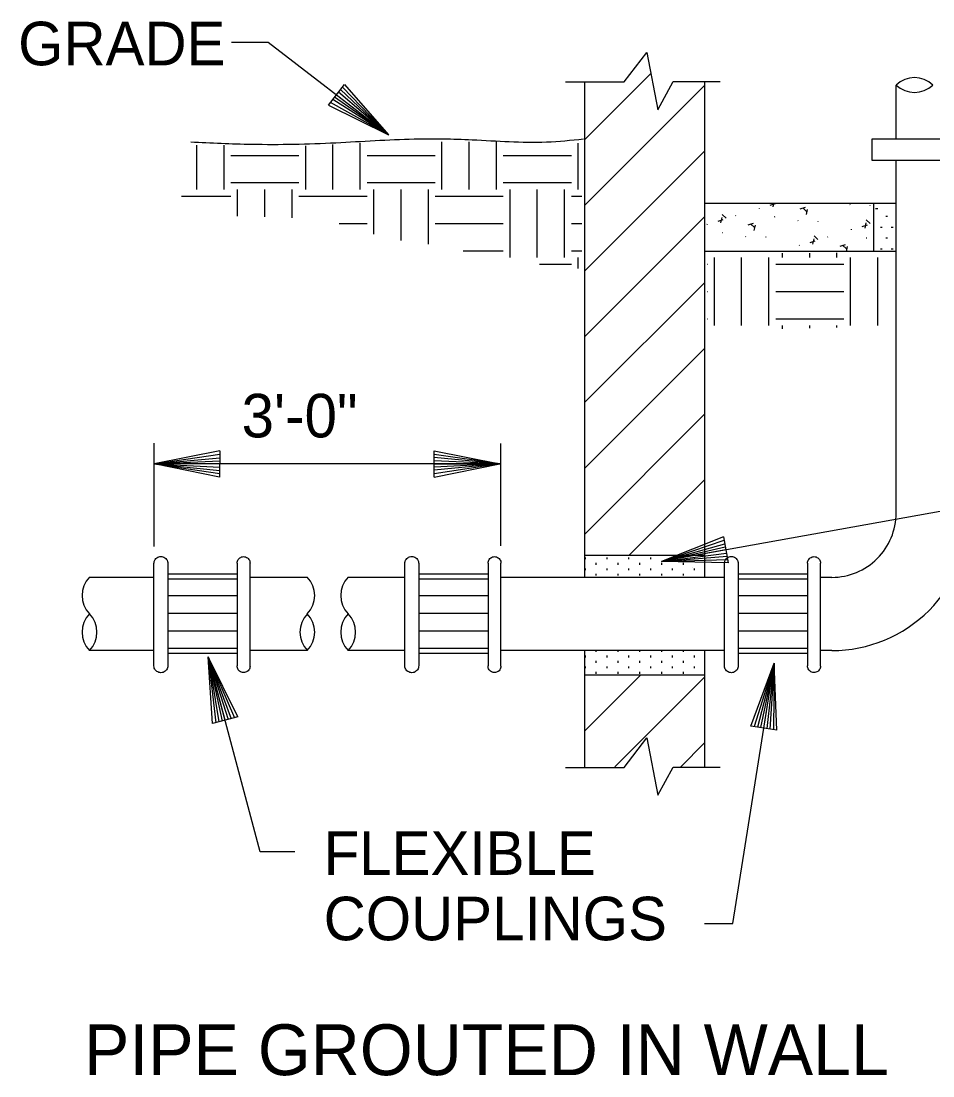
# Model space of a CAD drawing. Extents: x 10040.55 to 10045.84, y 10033.26 to 10035.76.
# Drawn here: x 10041.296 to 10041.5052, y 10033.7217 to 10033.9638 of the extents above; entities that cross this region are included whole.
import ezdxf

# ---------------------------------------------------------------- set-up
doc = ezdxf.new("R2010")
doc.units = 0
doc.layers.add('Level 2', color=7, linetype='Continuous')

msp = doc.modelspace()

# ---------------------------------------------------------------- linework, layer by layer
at = {"layer": 'Level 2'}
for p, q in [((10041.42536, 10033.93666), (10041.4405, 10033.95179)), ((10041.36655, 10033.9445), (10041.37023, 10033.94928)), ((10041.37023, 10033.94928), (10041.38032, 10033.93772)), ((10041.42536, 10033.83615), (10041.42536, 10033.94986)), ((10041.42538, 10033.92157), (10041.4528, 10033.94901)), ((10041.4528, 10033.94986), (10041.4528, 10033.83615)), ((10041.49676, 10033.93668), (10041.49676, 10033.94913)), ((10041.36835, 10033.94688), (10041.38032, 10033.93772)), ((10041.38032, 10033.93772), (10041.36882, 10033.94747)), ((10041.38032, 10033.93772), (10041.36927, 10033.94806)), ((10041.38032, 10033.93772), (10041.36972, 10033.94864)), ((10041.36655, 10033.9445), (10041.38032, 10033.93772)), ((10041.38032, 10033.93772), (10041.36702, 10033.94511)), ((10041.38032, 10033.93772), (10041.36751, 10033.94579)), ((10041.38032, 10033.93772), (10041.36794, 10033.94631)), ((10041.33632, 10033.92517), (10041.33632, 10033.9353)), ((10041.34257, 10033.92517), (10041.34257, 10033.9353)), ((10041.36132, 10033.92517), (10041.36132, 10033.93514)), ((10041.36757, 10033.92517), (10041.36757, 10033.93546)), ((10041.37382, 10033.92517), (10041.37382, 10033.93577)), ((10041.39257, 10033.92517), (10041.39257, 10033.93607)), ((10041.39882, 10033.92517), (10041.39882, 10033.93609)), ((10041.40507, 10033.92517), (10041.40507, 10033.9362)), ((10041.42382, 10033.92517), (10041.42382, 10033.93582)), ((10041.34414, 10033.93298), (10041.35976, 10033.93298)), ((10041.37539, 10033.93298), (10041.39101, 10033.93298)), ((10041.40664, 10033.93298), (10041.42226, 10033.93298)), ((10041.42538, 10033.90649), (10041.4528, 10033.93393)), ((10041.49676, 10033.85089), (10041.49676, 10033.93191)), ((10041.34414, 10033.92673), (10041.35976, 10033.92673)), ((10041.3457, 10033.91904), (10041.3457, 10033.92517)), ((10041.35195, 10033.91885), (10041.35195, 10033.92517)), ((10041.3582, 10033.91866), (10041.3582, 10033.92517)), ((10041.37539, 10033.92673), (10041.39101, 10033.92673)), ((10041.37695, 10033.9149), (10041.37695, 10033.92517)), ((10041.3832, 10033.91343), (10041.3832, 10033.92517)), ((10041.38945, 10033.91257), (10041.38945, 10033.92517)), ((10041.40664, 10033.92673), (10041.42226, 10033.92673)), ((10041.4082, 10033.90954), (10041.4082, 10033.92517)), ((10041.41445, 10033.90954), (10041.41445, 10033.92517)), ((10041.4207, 10033.90954), (10041.4207, 10033.92517)), ((10041.33285, 10033.9236), (10041.34414, 10033.9236)), ((10041.35976, 10033.9236), (10041.37539, 10033.9236)), ((10041.39101, 10033.9236), (10041.40664, 10033.9236)), ((10041.42226, 10033.9236), (10041.42464, 10033.9236)), ((10041.4968, 10033.92197), (10041.4528, 10033.92197)), ((10041.4654, 10033.92079), (10041.46542, 10033.9209)), ((10041.46788, 10033.92156), (10041.46907, 10033.92193)), ((10041.46864, 10033.92197), (10041.46845, 10033.92116)), ((10041.4759, 10033.92099), (10041.4747, 10033.92063)), ((10041.47533, 10033.92092), (10041.47624, 10033.92007)), ((10041.47619, 10033.91938), (10041.47647, 10033.92059)), ((10041.48623, 10033.92161), (10041.48616, 10033.92169)), ((10041.49077, 10033.92156), (10041.49075, 10033.92146)), ((10041.49161, 10033.92197), (10041.49161, 10033.911)), ((10041.49206, 10033.92076), (10041.4926, 10033.92076)), ((10041.42538, 10033.89142), (10041.4528, 10033.91884)), ((10041.45593, 10033.91791), (10041.45711, 10033.91827)), ((10041.45676, 10033.91872), (10041.45648, 10033.91751)), ((10041.45774, 10033.91856), (10041.45683, 10033.91941)), ((10041.45991, 10033.91913), (10041.46003, 10033.91916)), ((10041.46892, 10033.91885), (10041.46882, 10033.91882)), ((10041.47427, 10033.91796), (10041.4742, 10033.91803)), ((10041.47881, 10033.91791), (10041.47879, 10033.91781)), ((10041.48983, 10033.9175), (10041.48955, 10033.91628)), ((10041.4908, 10033.91735), (10041.48989, 10033.91821)), ((10041.49441, 10033.91904), (10041.49482, 10033.91904)), ((10041.36897, 10033.91735), (10041.37539, 10033.91735)), ((10041.39101, 10033.91735), (10041.40664, 10033.91735)), ((10041.42226, 10033.91735), (10041.42464, 10033.91735)), ((10041.45344, 10033.91715), (10041.45346, 10033.91724)), ((10041.45697, 10033.9152), (10041.45686, 10033.91517)), ((10041.46394, 10033.91733), (10041.46274, 10033.91697)), ((10041.46338, 10033.91726), (10041.46428, 10033.91641)), ((10041.46423, 10033.91572), (10041.46451, 10033.91694)), ((10041.48651, 10033.91592), (10041.48653, 10033.91602)), ((10041.48898, 10033.91668), (10041.49017, 10033.91704)), ((10041.49316, 10033.91654), (10041.49357, 10033.91654)), ((10041.49566, 10033.91654), (10041.49607, 10033.91654)), ((10041.46231, 10033.91429), (10041.46224, 10033.91436)), ((10041.46685, 10033.91426), (10041.46683, 10033.91416)), ((10041.47702, 10033.91302), (10041.47822, 10033.9134)), ((10041.47788, 10033.91385), (10041.47759, 10033.91264)), ((10041.47884, 10033.9137), (10041.47793, 10033.91454)), ((10041.481, 10033.91424), (10041.48113, 10033.91428)), ((10041.49002, 10033.91398), (10041.48992, 10033.91395)), ((10041.49441, 10033.91404), (10041.49482, 10033.91404)), ((10041.39747, 10033.9111), (10041.40664, 10033.9111)), ((10041.42226, 10033.9111), (10041.42464, 10033.9111)), ((10041.4528, 10033.91099), (10041.4968, 10033.91099)), ((10041.4707, 10033.90954), (10041.4707, 10033.91051)), ((10041.47454, 10033.91227), (10041.47457, 10033.91236)), ((10041.47695, 10033.90954), (10041.47695, 10033.91056)), ((10041.4832, 10033.90954), (10041.4832, 10033.91061)), ((10041.48504, 10033.91246), (10041.48384, 10033.91209)), ((10041.48447, 10033.9124), (10041.48539, 10033.91154)), ((10041.48535, 10033.91092), (10041.48561, 10033.91206)), ((10041.49316, 10033.91154), (10041.49357, 10033.91154)), ((10041.49566, 10033.91154), (10041.49607, 10033.91154)), ((10041.41493, 10033.90798), (10041.42226, 10033.90798)), ((10041.42382, 10033.90699), (10041.42382, 10033.90954)), ((10041.45343, 10033.90798), (10041.45351, 10033.90798)), ((10041.45507, 10033.89392), (10041.45507, 10033.90954)), ((10041.46132, 10033.89392), (10041.46132, 10033.90954)), ((10041.46757, 10033.89392), (10041.46757, 10033.90954)), ((10041.46914, 10033.90798), (10041.48476, 10033.90798)), ((10041.48632, 10033.89392), (10041.48632, 10033.90954)), ((10041.49257, 10033.89392), (10041.49257, 10033.90954)), ((10041.42538, 10033.87633), (10041.4528, 10033.90376)), ((10041.45343, 10033.90173), (10041.45351, 10033.90173)), ((10041.46914, 10033.90173), (10041.48476, 10033.90173)), ((10041.45343, 10033.89548), (10041.45351, 10033.89548)), ((10041.46914, 10033.89548), (10041.48476, 10033.89548)), ((10041.4707, 10033.89316), (10041.4707, 10033.89392)), ((10041.47695, 10033.89332), (10041.47695, 10033.89392)), ((10041.4832, 10033.89349), (10041.4832, 10033.89392)), ((10041.42539, 10033.86125), (10041.4528, 10033.88867)), ((10041.42539, 10033.84617), (10041.45281, 10033.87358)), ((10041.32653, 10033.84326), (10041.32653, 10033.86696)), ((10041.40609, 10033.84336), (10041.40609, 10033.86685)), ((10041.34158, 10033.86516), (10041.32653, 10033.86216)), ((10041.32653, 10033.86216), (10041.34158, 10033.8644)), ((10041.34158, 10033.86516), (10041.34157, 10033.85914)), ((10041.39077, 10033.85916), (10041.39078, 10033.86518)), ((10041.40582, 10033.86216), (10041.39077, 10033.86436)), ((10041.39078, 10033.86518), (10041.40582, 10033.86216)), ((10041.32653, 10033.86216), (10041.3416, 10033.86355)), ((10041.32653, 10033.86216), (10041.34158, 10033.86288)), ((10041.34159, 10033.86218), (10041.32653, 10033.86216)), ((10041.40582, 10033.86216), (10041.32653, 10033.86216)), ((10041.34157, 10033.85914), (10041.32653, 10033.86216)), ((10041.32653, 10033.86216), (10041.34159, 10033.86068)), ((10041.32653, 10033.86216), (10041.34158, 10033.85995)), ((10041.32653, 10033.86216), (10041.34158, 10033.86142)), ((10041.40582, 10033.86216), (10041.39075, 10033.86076)), ((10041.40582, 10033.86216), (10041.39076, 10033.86364)), ((10041.39076, 10033.86214), (10041.40582, 10033.86216)), ((10041.40582, 10033.86216), (10041.39077, 10033.8629)), ((10041.39077, 10033.85916), (10041.40582, 10033.86216)), ((10041.40582, 10033.86216), (10041.39077, 10033.86144)), ((10041.40582, 10033.86216), (10041.39077, 10033.85992)), ((10041.43544, 10033.84113), (10041.45281, 10033.8585)), ((10041.55081, 10033.85919), (10041.4429, 10033.83979)), ((10041.45719, 10033.84541), (10041.4429, 10033.83979)), ((10041.45719, 10033.84541), (10041.45824, 10033.83948)), ((10041.4429, 10033.83979), (10041.45732, 10033.84466)), ((10041.4429, 10033.83979), (10041.45749, 10033.84383)), ((10041.4429, 10033.83979), (10041.45758, 10033.84317)), ((10041.45772, 10033.84248), (10041.4429, 10033.83979)), ((10041.4528, 10033.84113), (10041.42539, 10033.84113)), ((10041.42548, 10033.84029), (10041.42548, 10033.84071)), ((10041.43048, 10033.84029), (10041.43048, 10033.84071)), ((10041.43548, 10033.84029), (10041.43548, 10033.84071)), ((10041.44048, 10033.84029), (10041.44048, 10033.84071)), ((10041.4429, 10033.83979), (10041.45784, 10033.84173)), ((10041.4429, 10033.83979), (10041.45799, 10033.841)), ((10041.4429, 10033.83979), (10041.4581, 10033.84028)), ((10041.44548, 10033.84029), (10041.44548, 10033.84071)), ((10041.45048, 10033.84029), (10041.45048, 10033.84071)), ((10041.32649, 10033.81582), (10041.32649, 10033.83933)), ((10041.32968, 10033.83933), (10041.32968, 10033.81589)), ((10041.34557, 10033.83941), (10041.34557, 10033.81582)), ((10041.34855, 10033.81576), (10041.34855, 10033.83941)), ((10041.38406, 10033.81582), (10041.38406, 10033.83933)), ((10041.38724, 10033.83933), (10041.38724, 10033.81589)), ((10041.40314, 10033.83941), (10041.40314, 10033.81582)), ((10041.40611, 10033.81576), (10041.40611, 10033.83941)), ((10041.42548, 10033.83779), (10041.42548, 10033.83821)), ((10041.42798, 10033.83904), (10041.42798, 10033.83946)), ((10041.43048, 10033.83779), (10041.43048, 10033.83821)), ((10041.43298, 10033.83904), (10041.43298, 10033.83946)), ((10041.43548, 10033.83779), (10041.43548, 10033.83821)), ((10041.43798, 10033.83904), (10041.43798, 10033.83946)), ((10041.44048, 10033.83779), (10041.44048, 10033.83821)), ((10041.45824, 10033.83948), (10041.4429, 10033.83979)), ((10041.44298, 10033.83904), (10041.44298, 10033.83946)), ((10041.44548, 10033.83779), (10041.44548, 10033.83821)), ((10041.44798, 10033.83904), (10041.44798, 10033.83946)), ((10041.45006, 10033.83849), (10041.45006, 10033.83849)), ((10041.45048, 10033.83779), (10041.45048, 10033.83821)), ((10041.45738, 10033.81582), (10041.45738, 10033.83933)), ((10041.46055, 10033.83933), (10041.46055, 10033.81589)), ((10041.47645, 10033.83941), (10041.47645, 10033.81582)), ((10041.47943, 10033.81576), (10041.47943, 10033.83941)), ((10041.32649, 10033.83615), (10041.31171, 10033.83615)), ((10041.34557, 10033.83689), (10041.32968, 10033.83689)), ((10041.34557, 10033.83576), (10041.32968, 10033.83576)), ((10041.36168, 10033.83615), (10041.34855, 10033.83615)), ((10041.38406, 10033.83615), (10041.37105, 10033.83615)), ((10041.40314, 10033.83689), (10041.38724, 10033.83689)), ((10041.40314, 10033.83576), (10041.38724, 10033.83576)), ((10041.4574, 10033.83615), (10041.40611, 10033.83615)), ((10041.42798, 10033.83654), (10041.42798, 10033.83696)), ((10041.43298, 10033.83654), (10041.43298, 10033.83696)), ((10041.43798, 10033.83654), (10041.43798, 10033.83696)), ((10041.44298, 10033.83654), (10041.44298, 10033.83696)), ((10041.44798, 10033.83654), (10041.44798, 10033.83696)), ((10041.47645, 10033.83689), (10041.46055, 10033.83689)), ((10041.47645, 10033.83576), (10041.46055, 10033.83576)), ((10041.48203, 10033.83615), (10041.47945, 10033.83615)), ((10041.34557, 10033.83192), (10041.32968, 10033.83192)), ((10041.40314, 10033.83192), (10041.38724, 10033.83192)), ((10041.47645, 10033.83192), (10041.46055, 10033.83192)), ((10041.34557, 10033.82788), (10041.32968, 10033.82788)), ((10041.40314, 10033.82788), (10041.38724, 10033.82788)), ((10041.47645, 10033.82788), (10041.46055, 10033.82788)), ((10041.34557, 10033.82377), (10041.32968, 10033.82377)), ((10041.40314, 10033.82377), (10041.38724, 10033.82377)), ((10041.47645, 10033.82377), (10041.46055, 10033.82377)), ((10041.32649, 10033.81934), (10041.31171, 10033.81934)), ((10041.34557, 10033.8198), (10041.32968, 10033.8198)), ((10041.32968, 10033.81874), (10041.34557, 10033.81874)), ((10041.36168, 10033.81934), (10041.34855, 10033.81934)), ((10041.38406, 10033.81934), (10041.37105, 10033.81934)), ((10041.40314, 10033.8198), (10041.38724, 10033.8198)), ((10041.38724, 10033.81874), (10041.40314, 10033.81874)), ((10041.4574, 10033.81934), (10041.40611, 10033.81934)), ((10041.42536, 10033.79253), (10041.42536, 10033.81934)), ((10041.42798, 10033.81904), (10041.42798, 10033.81918)), ((10041.43298, 10033.81904), (10041.43298, 10033.81924)), ((10041.43798, 10033.81904), (10041.43798, 10033.81929)), ((10041.44298, 10033.81904), (10041.44298, 10033.81934)), ((10041.44798, 10033.81904), (10041.44798, 10033.81941)), ((10041.4528, 10033.81934), (10041.4528, 10033.79253)), ((10041.47645, 10033.8198), (10041.46055, 10033.8198)), ((10041.46055, 10033.81874), (10041.47645, 10033.81874)), ((10041.48203, 10033.81934), (10041.47945, 10033.81934)), ((10041.34285, 10033.80335), (10041.33895, 10033.81791)), ((10041.33991, 10033.80259), (10041.33895, 10033.81791)), ((10041.34573, 10033.80414), (10041.33895, 10033.81791)), ((10041.33895, 10033.81791), (10041.3414, 10033.80297)), ((10041.33895, 10033.81791), (10041.34418, 10033.8037)), ((10041.33895, 10033.81791), (10041.3407, 10033.80279)), ((10041.33895, 10033.81791), (10041.34211, 10033.80317)), ((10041.33895, 10033.81791), (10041.34353, 10033.80354)), ((10041.33895, 10033.81791), (10041.34499, 10033.80394)), ((10041.42548, 10033.81779), (10041.42548, 10033.81821)), ((10041.42798, 10033.81654), (10041.42798, 10033.81696)), ((10041.43048, 10033.81779), (10041.43048, 10033.81821)), ((10041.43298, 10033.81654), (10041.43298, 10033.81696)), ((10041.43548, 10033.81779), (10041.43548, 10033.81821)), ((10041.43798, 10033.81654), (10041.43798, 10033.81696)), ((10041.44048, 10033.81779), (10041.44048, 10033.81821)), ((10041.44298, 10033.81654), (10041.44298, 10033.81696)), ((10041.44548, 10033.81779), (10041.44548, 10033.81821)), ((10041.44798, 10033.81654), (10041.44798, 10033.81696)), ((10041.45048, 10033.81779), (10041.45048, 10033.81821)), ((10041.46341, 10033.80203), (10041.46875, 10033.81642)), ((10041.46875, 10033.81642), (10041.46422, 10033.8019)), ((10041.46875, 10033.81642), (10041.46494, 10033.80177)), ((10041.46875, 10033.81642), (10041.46567, 10033.80167)), ((10041.46642, 10033.80153), (10041.46875, 10033.81642)), ((10041.46875, 10033.81642), (10041.46711, 10033.80144)), ((10041.46875, 10033.81642), (10041.46777, 10033.80131)), ((10041.46875, 10033.81642), (10041.4686, 10033.8012)), ((10041.46936, 10033.80107), (10041.46875, 10033.81642)), ((10041.4528, 10033.81367), (10041.42535, 10033.81367)), ((10041.42538, 10033.8009), (10041.43814, 10033.81367)), ((10041.42548, 10033.81529), (10041.42548, 10033.81571)), ((10041.42798, 10033.81404), (10041.42798, 10033.81446)), ((10041.43048, 10033.81529), (10041.43048, 10033.81571)), ((10041.43298, 10033.81404), (10041.43298, 10033.81446)), ((10041.43548, 10033.81529), (10041.43548, 10033.81571)), ((10041.43798, 10033.81404), (10041.43798, 10033.81446)), ((10041.44048, 10033.81529), (10041.44048, 10033.81571)), ((10041.44298, 10033.81404), (10041.44298, 10033.81446)), ((10041.44548, 10033.81529), (10041.44548, 10033.81571)), ((10041.44798, 10033.81404), (10041.44798, 10033.81446)), ((10041.45048, 10033.81529), (10041.45048, 10033.81571)), ((10041.4322, 10033.79264), (10041.4528, 10033.81324)), ((10041.34573, 10033.80414), (10041.33991, 10033.80259)), ((10041.46936, 10033.80107), (10041.46341, 10033.80203)), ((10041.44726, 10033.79261), (10041.4528, 10033.79816))]:
    msp.add_line(p, q, dxfattribs=at)
for points in [[(10041.34427, 10033.95895), (10041.35267, 10033.95895), (10041.38032, 10033.93772)], [(10041.42093, 10033.94984), (10041.43441, 10033.94984), (10041.43958, 10033.95661), (10041.44209, 10033.94345), (10041.4456, 10033.94992), (10041.45642, 10033.94992)], [(10041.32649, 10033.83933), (10041.32651, 10033.83958), (10041.32657, 10033.83982), (10041.32667, 10033.84006), (10041.3268, 10033.84027), (10041.32696, 10033.84046), (10041.32715, 10033.84063), (10041.32736, 10033.84075), (10041.32759, 10033.84084), (10041.32783, 10033.84091), (10041.32808, 10033.84093), (10041.32833, 10033.84091), (10041.32857, 10033.84084), (10041.3288, 10033.84075), (10041.32902, 10033.84063), (10041.32921, 10033.84046), (10041.32936, 10033.84027), (10041.3295, 10033.84006), (10041.32959, 10033.83982), (10041.32966, 10033.83958), (10041.32968, 10033.83933)], [(10041.34557, 10033.83941), (10041.34558, 10033.83964), (10041.34565, 10033.83986), (10041.34573, 10033.84008), (10041.34585, 10033.84028), (10041.34601, 10033.84046), (10041.34619, 10033.8406), (10041.34639, 10033.84073), (10041.34659, 10033.84082), (10041.34682, 10033.84088), (10041.34706, 10033.8409), (10041.34729, 10033.84088), (10041.34752, 10033.84082), (10041.34774, 10033.84073), (10041.34794, 10033.8406), (10041.34811, 10033.84046), (10041.34826, 10033.84028), (10041.34839, 10033.84008), (10041.34848, 10033.83986), (10041.34853, 10033.83964), (10041.34855, 10033.83941)], [(10041.38406, 10033.83933), (10041.38407, 10033.83958), (10041.38414, 10033.83982), (10041.38423, 10033.84006), (10041.38436, 10033.84027), (10041.38452, 10033.84046), (10041.38471, 10033.84063), (10041.38493, 10033.84075), (10041.38516, 10033.84084), (10041.3854, 10033.84091), (10041.38565, 10033.84093), (10041.3859, 10033.84091), (10041.38614, 10033.84084), (10041.38636, 10033.84075), (10041.38658, 10033.84063), (10041.38677, 10033.84046), (10041.38694, 10033.84027), (10041.38706, 10033.84006), (10041.38716, 10033.83982), (10041.38722, 10033.83958), (10041.38724, 10033.83933)], [(10041.40314, 10033.83941), (10041.40315, 10033.83964), (10041.40321, 10033.83986), (10041.40329, 10033.84008), (10041.40342, 10033.84028), (10041.40357, 10033.84046), (10041.40375, 10033.8406), (10041.40395, 10033.84073), (10041.40417, 10033.84082), (10041.40439, 10033.84088), (10041.40463, 10033.8409), (10041.40485, 10033.84088), (10041.40508, 10033.84082), (10041.4053, 10033.84073), (10041.4055, 10033.8406), (10041.40568, 10033.84046), (10041.40583, 10033.84028), (10041.40595, 10033.84008), (10041.40604, 10033.83986), (10041.40609, 10033.83964), (10041.40611, 10033.83941)], [(10041.45738, 10033.83933), (10041.4574, 10033.83958), (10041.45745, 10033.83982), (10041.45754, 10033.84006), (10041.45768, 10033.84027), (10041.45783, 10033.84046), (10041.45803, 10033.84063), (10041.45824, 10033.84075), (10041.45847, 10033.84084), (10041.45871, 10033.84091), (10041.45896, 10033.84093), (10041.45921, 10033.84091), (10041.45945, 10033.84084), (10041.45968, 10033.84075), (10041.4599, 10033.84063), (10041.46008, 10033.84046), (10041.46025, 10033.84027), (10041.46038, 10033.84006), (10041.46047, 10033.83982), (10041.46053, 10033.83958), (10041.46055, 10033.83933)], [(10041.47645, 10033.83941), (10041.47647, 10033.83964), (10041.47652, 10033.83986), (10041.4766, 10033.84008), (10041.47673, 10033.84028), (10041.47689, 10033.84046), (10041.47706, 10033.8406), (10041.47726, 10033.84073), (10041.47748, 10033.84082), (10041.47771, 10033.84088), (10041.47794, 10033.8409), (10041.47817, 10033.84088), (10041.4784, 10033.84082), (10041.47861, 10033.84073), (10041.47881, 10033.8406), (10041.47899, 10033.84046), (10041.47915, 10033.84028), (10041.47926, 10033.84008), (10041.47935, 10033.83986), (10041.47941, 10033.83964), (10041.47943, 10033.83941)], [(10041.32968, 10033.81589), (10041.32966, 10033.81565), (10041.3296, 10033.8154), (10041.32951, 10033.81517), (10041.32939, 10033.81495), (10041.32923, 10033.81476), (10041.32904, 10033.81459), (10041.32883, 10033.81446), (10041.3286, 10033.81435), (10041.32836, 10033.81429), (10041.32811, 10033.81427), (10041.32786, 10033.81428), (10041.32763, 10033.81433), (10041.3274, 10033.81443), (10041.32718, 10033.81455), (10041.32698, 10033.81471), (10041.32681, 10033.8149), (10041.32668, 10033.8151), (10041.32658, 10033.81533), (10041.32652, 10033.81557), (10041.32649, 10033.81582)], [(10041.35884, 10033.77315), (10041.35089, 10033.77315), (10041.33895, 10033.81791)], [(10041.34855, 10033.81576), (10041.34852, 10033.81552), (10041.34847, 10033.8153), (10041.34838, 10033.81508), (10041.34825, 10033.81489), (10041.34809, 10033.81471), (10041.34791, 10033.81456), (10041.34771, 10033.81445), (10041.34749, 10033.81436), (10041.34726, 10033.81431), (10041.34702, 10033.8143), (10041.34679, 10033.81432), (10041.34656, 10033.81439), (10041.34635, 10033.81448), (10041.34616, 10033.8146), (10041.34598, 10033.81476), (10041.34583, 10033.81494), (10041.34572, 10033.81515), (10041.34564, 10033.81536), (10041.34558, 10033.81559), (10041.34557, 10033.81582)], [(10041.38724, 10033.81589), (10041.38722, 10033.81565), (10041.38717, 10033.8154), (10041.38708, 10033.81517), (10041.38695, 10033.81495), (10041.38679, 10033.81476), (10041.3866, 10033.81459), (10041.3864, 10033.81446), (10041.38617, 10033.81435), (10041.38593, 10033.81429), (10041.38568, 10033.81427), (10041.38543, 10033.81428), (10041.38519, 10033.81433), (10041.38496, 10033.81443), (10041.38474, 10033.81455), (10041.38454, 10033.81471), (10041.38439, 10033.8149), (10041.38425, 10033.8151), (10041.38415, 10033.81533), (10041.38408, 10033.81557), (10041.38406, 10033.81582)], [(10041.40611, 10033.81576), (10041.40609, 10033.81552), (10041.40603, 10033.8153), (10041.40594, 10033.81508), (10041.40581, 10033.81489), (10041.40566, 10033.81471), (10041.40547, 10033.81456), (10041.40527, 10033.81445), (10041.40505, 10033.81436), (10041.40482, 10033.81431), (10041.40459, 10033.8143), (10041.40435, 10033.81432), (10041.40414, 10033.81439), (10041.40392, 10033.81448), (10041.40372, 10033.8146), (10041.40354, 10033.81476), (10041.4034, 10033.81494), (10041.40328, 10033.81515), (10041.4032, 10033.81536), (10041.40315, 10033.81559), (10041.40314, 10033.81582)], [(10041.45284, 10033.75673), (10041.4593, 10033.75673), (10041.46875, 10033.81642)], [(10041.46055, 10033.81589), (10041.46053, 10033.81565), (10041.46048, 10033.8154), (10041.4604, 10033.81517), (10041.46027, 10033.81495), (10041.4601, 10033.81476), (10041.45992, 10033.81459), (10041.45971, 10033.81446), (10041.45948, 10033.81435), (10041.45924, 10033.81429), (10041.45899, 10033.81427), (10041.45874, 10033.81428), (10041.4585, 10033.81433), (10041.45827, 10033.81443), (10041.45805, 10033.81455), (10041.45786, 10033.81471), (10041.4577, 10033.8149), (10041.45756, 10033.8151), (10041.45746, 10033.81533), (10041.4574, 10033.81557), (10041.45738, 10033.81582)], [(10041.47943, 10033.81576), (10041.47941, 10033.81552), (10041.47934, 10033.8153), (10041.47925, 10033.81508), (10041.47913, 10033.81489), (10041.47897, 10033.81471), (10041.47878, 10033.81456), (10041.47858, 10033.81445), (10041.47836, 10033.81436), (10041.47814, 10033.81431), (10041.47791, 10033.8143), (10041.47767, 10033.81432), (10041.47745, 10033.81439), (10041.47723, 10033.81448), (10041.47703, 10033.8146), (10041.47685, 10033.81476), (10041.47671, 10033.81494), (10041.47659, 10033.81515), (10041.47651, 10033.81536), (10041.47646, 10033.81559), (10041.47645, 10033.81582)], [(10041.42093, 10033.79254), (10041.43441, 10033.79254), (10041.43958, 10033.79931), (10041.44209, 10033.78615), (10041.4456, 10033.79261), (10041.45642, 10033.79261)]]:
    msp.add_lwpolyline(points, dxfattribs=at)
msp.add_lwpolyline([(10041.49119, 10033.93668), (10041.49119, 10033.93191), (10041.51927, 10033.93191), (10041.51927, 10033.93668)], close=True, dxfattribs=at)
for centre, radius, start, end in [((10041.50098, 10033.94476), 0.00607, 45.9775, 134.0212), ((10041.50098, 10033.95349), 0.00607, 225.9788, 314.0225), ((10041.48203, 10033.85088), 0.03154, 269.9817, 0), ((10041.48203, 10033.85088), 0.01473, 269.9827, 360), ((10041.31608, 10033.832), 0.00607, 135.9788, 224.0225), ((10041.35731, 10033.832), 0.00607, 315.9775, 44.0212), ((10041.37542, 10033.832), 0.00607, 135.9788, 224.0225), ((10041.31608, 10033.82355), 0.00607, 135.9775, 224.0212), ((10041.30734, 10033.82355), 0.00607, 315.9788, 44.0225), ((10041.36605, 10033.82355), 0.00607, 135.9775, 224.0212), ((10041.35731, 10033.82355), 0.00607, 315.9788, 44.0225), ((10041.37542, 10033.82355), 0.00607, 135.9775, 224.0212), ((10041.36668, 10033.82355), 0.00607, 315.9788, 44.0225)]:
    msp.add_arc(centre, radius, start, end, dxfattribs=at)
msp.add_spline([(10041.42501, 10033.93668), (10041.41656, 10033.93599), (10041.39948, 10033.9365), (10041.38619, 10033.93668), (10041.36824, 10033.93581), (10041.34892, 10033.93547), (10041.33494, 10033.93599)], degree=3, dxfattribs=at)

# ---------------------------------------------------------------- texts
for s, height, p in [('GRADE', 0.01, (10041.29534, 10033.95365)), ('3\'-0"', 0.01, (10041.3466, 10033.86826)), ('FLEXIBLE', 0.01, (10041.36543, 10033.76786)), ('COUPLINGS', 0.01, (10041.36543, 10033.75286)), ('PIPE GROUTED IN WALL', 0.0116667, (10041.31044, 10033.72191))]:
    msp.add_text(s, height=height, dxfattribs=at).set_placement(p)

doc.saveas('drawing.dxf')
